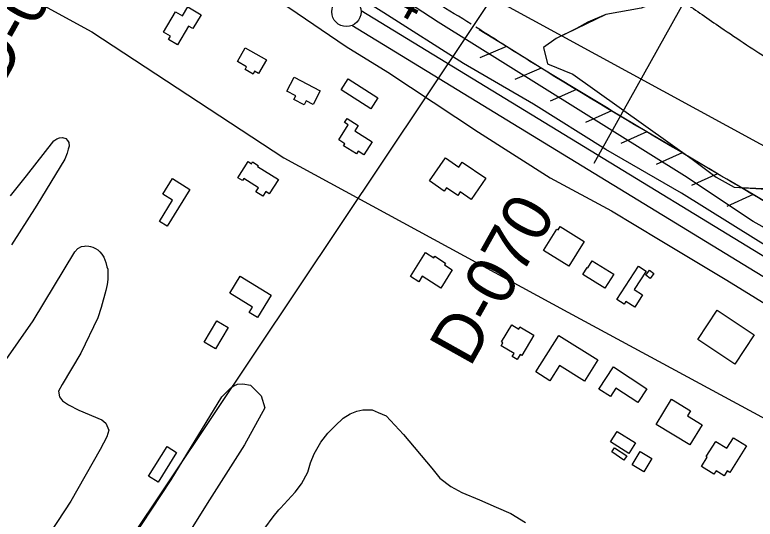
# Model space of a CAD drawing. Extents: x 3855477 to 3893699, y 299188 to 325115.
# Drawn here: x 3860680 to 3861941, y 312808 to 313668 of the extents above; entities that cross this region are included whole.
import ezdxf

# ---------------------------------------------------------------- set-up
doc = ezdxf.new("R2010")
doc.units = 0
for name, color, linetype in [('V-BLDG-OTLN', 7, 'Continuous'), ('V-LEVE-TOET', 7, 'Continuous'), ('V-RIVR-EDGE', 7, 'Continuous'), ('V-RIVR-RANG', 7, 'Continuous'), ('V-RIVR-RANG-IDEN', 7, 'Continuous'), ('V-ROAD-CNTR', 7, 'Continuous'), ('V-RRAP-FSHR', 7, 'Continuous'), ('V-SITE-VEGE', 7, 'Continuous'), ('V-SURV-LINE', 7, 'Continuous'), ('V-TOPO-SHOR', 7, 'Continuous')]:
    doc.layers.add(name, color=color, linetype=linetype)

msp = doc.modelspace()

# ---------------------------------------------------------------- linework, layer by layer
at = {"layer": 'V-BLDG-OTLN'}
for points in [[(3860933.2, 313638.2), (3860953.7, 313672.9), (3860965.7, 313665.8), (3860974.7, 313681.2), (3860997.2, 313667.9), (3860983.2, 313644.2), (3860976.1, 313648.4), (3860957.2, 313616.5), (3860941.8, 313625.6), (3860945.1, 313631.2)], [(3861072.6, 313611.6), (3861108.7, 313591.1), (3861095.3, 313567.5), (3861088.5, 313571.4), (3861085.9, 313566.8), (3861072.2, 313574.5), (3861074.8, 313579.1), (3861059.2, 313588)], [(3861155.8, 313561.4), (3861200.3, 313538.3), (3861188.2, 313515.1), (3861176.4, 313521.3), (3861172.8, 313514.2), (3861155.4, 313523.2), (3861158.6, 313529.4), (3861143.3, 313537.3)], [(3861286.3, 313507.5), (3861235.6, 313539.9), (3861247.7, 313558.8), (3861298.4, 313526.4)], [(3861288.4, 313451.4), (3861274.4, 313429.3), (3861264.8, 313435.4), (3861261.8, 313430.7), (3861240, 313444.5), (3861242.2, 313448.1), (3861231.7, 313454.7), (3861247.9, 313480.2), (3861241.6, 313484.3), (3861245.9, 313490.9), (3861264.5, 313479.1), (3861258.9, 313470.2)], [(3861386.2, 313384.6), (3861413.3, 313424), (3861436.4, 313408.2), (3861442.1, 313416.5), (3861481.9, 313389.1), (3861457.2, 313353.1), (3861438.5, 313365.8), (3861434.3, 313359.7), (3861415.1, 313372.9), (3861411.2, 313367.4)], [(3861128.9, 313387), (3861113.5, 313362.6), (3861107.5, 313366.4), (3861102.6, 313358.7), (3861090.6, 313366.3), (3861094.8, 313372.9), (3861070, 313388.6), (3861067.9, 313385.2), (3861059.9, 313390.2), (3861077.2, 313417.7), (3861083.1, 313414), (3861085.1, 313417.1), (3861094.6, 313411.1), (3861093.5, 313409.4)], [(3860978.4, 313370), (3860939.4, 313307.6), (3860926.3, 313315.8), (3860948.8, 313351.7), (3860932.2, 313362.2), (3860948.7, 313388.6)], [(3861580.4, 313265.9), (3861603.2, 313302.7), (3861605.5, 313301.3), (3861609, 313306.9), (3861649.6, 313281.6), (3861623.3, 313239.2)], [(3861353.9, 313222), (3861379.6, 313262.6), (3861393.6, 313253.7), (3861395.3, 313256.5), (3861413.7, 313244.8), (3861411.7, 313241.6), (3861425.1, 313233.1), (3861405.6, 313202.2), (3861374, 313222.2), (3861368.1, 313213)], [(3861663.5, 313248.7), (3861700.1, 313225.7), (3861685, 313201.7), (3861647.2, 313225.5), (3861654.5, 313237.3), (3861655.8, 313236.5)], [(3861705.4, 313182.4), (3861741.9, 313239.2), (3861754.9, 313230.9), (3861734.9, 313199.7), (3861749.1, 313190.6), (3861735.7, 313169.8), (3861720.7, 313179.5), (3861717.6, 313174.6)], [(3861064, 313222.3), (3861116.5, 313189.9), (3861093.1, 313152), (3861079.4, 313160.4), (3861085, 313169.4), (3861046.2, 313193.4)], [(3861768.1, 313227.1), (3861761.8, 313218.7), (3861754.7, 313224), (3861760.9, 313232.4)], [(3861906, 313072.5), (3861842.9, 313114.4), (3861876.1, 313164.4), (3861939.2, 313122.5)], [(3861043.4, 313135), (3861021.7, 313098.7), (3861002.7, 313110.1), (3861024.3, 313146.4)], [(3861563.8, 313121.8), (3861543.2, 313087.3), (3861540.7, 313088.8), (3861535.6, 313080.3), (3861527, 313085.4), (3861530.2, 313090.7), (3861508.1, 313103.9), (3861511.2, 313109), (3861509, 313110.3), (3861526.3, 313139.4), (3861538.2, 313132.3), (3861540.3, 313135.8)], [(3861606.7, 313121.6), (3861673.1, 313079.6), (3861650.1, 313043.3), (3861607.5, 313070.2), (3861591, 313044.2), (3861567.2, 313059.3)], [(3861699.3, 313067.9), (3861756.3, 313030.6), (3861740.8, 313006.9), (3861703.3, 313031.4), (3861694.2, 313017.3), (3861674.6, 313030.1)], [(3861825.4, 312984.6), (3861850.4, 312969.4), (3861829.4, 312934.9), (3861772, 312969.9), (3861798.1, 313012.7), (3861830.5, 312992.9)], [(3861705.6, 312958), (3861736.8, 312938.4), (3861725.4, 312920.3), (3861694.2, 312939.9)], [(3861903.7, 312947.1), (3861926, 312933.1), (3861897.4, 312887.8), (3861893.1, 312890.6), (3861887.9, 312882.4), (3861874.3, 312891), (3861870.5, 312884.9), (3861849.2, 312898.3), (3861859, 312913.8), (3861857.3, 312914.9), (3861873.7, 312941), (3861892.4, 312929.2)], [(3860939.4, 312932.2), (3860955.7, 312922), (3860924.1, 312871.2), (3860907.7, 312881.4)], [(3861701.3, 312930.2), (3861722, 312916.2), (3861717.2, 312909.1), (3861696.6, 312923.1)], [(3861744.9, 312923.8), (3861764.8, 312911.8), (3861751.1, 312889.1), (3861731.3, 312901.1)]]:
    msp.add_lwpolyline(points, close=True, dxfattribs=at)
at = {"layer": 'V-LEVE-TOET'}
for points in [[(3862242.2, 313100.5), (3862093.7, 313191.4), (3861941.9, 313285.1), (3861815.6, 313363.6), (3861686.6, 313438.4), (3861563.5, 313515.7), (3861444.2, 313584.7), (3861308.7, 313671.1), (3861176.5, 313754.8), (3861033.5, 313846.5), (3860865.7, 313952.6), (3860666.5, 314081.9), (3860455.2, 314218.1), (3860280.2, 314328.3), (3860126.5, 314425.9), (3859979.2, 314523.5), (3859824, 314623.6), (3859706.2, 314705.8), (3859691.7, 314716.1), (3859678.8, 314724.5), (3859655.1, 314737.6), (3859575.8, 314787.4), (3859572.3, 314789.8)], [(3860660.7, 313988.8), (3860749.4, 313935.7), (3860881.4, 313854.3), (3860919.6, 313826.5), (3860984.4, 313781.3), (3861077.1, 313725), (3861146.5, 313680.2), (3861244.1, 313613.7), (3861315.4, 313570), (3861469.8, 313467.8), (3861591.7, 313389.8), (3861695.9, 313333.8), (3861779.1, 313284), (3861892.7, 313215.5), (3861990.2, 313155.4)]]:
    msp.add_lwpolyline(points, dxfattribs=at)
at = {"layer": 'V-RIVR-EDGE'}
msp.add_spline([(3861230.3, 314081.8), (3861249.7, 314067.2), (3861271, 314053.5), (3861295.2, 314036.5), (3861330.6, 314011.6), (3861359.2, 313991.2), (3861386.9, 313974.6), (3861437.8, 313938), (3861477, 313912.7), (3861508.6, 313892.7), (3861539.1, 313865.9), (3861562.8, 313845.9), (3861578.8, 313831.8), (3861602.1, 313814.3), (3861632.6, 313795.8), (3861647.2, 313793.8), (3861661.3, 313794.2), (3861675.4, 313788.4), (3861690.4, 313775.2), (3861787.8, 313710.9), (3861820.8, 313688.4), (3861850.4, 313668), (3861882.4, 313646), (3861926, 313616.8), (3861968.7, 313589), (3861997.3, 313571.5), (3862045.8, 313537.8), (3862083.6, 313512), (3862115.6, 313489.6), (3862218.4, 313424.3), (3862268.8, 313390.6), (3862319.7, 313355.5), (3862352.2, 313333.6), (3862383.2, 313312.1), (3862411.3, 313296.1), (3862449.2, 313274.1), (3862514.1, 313236.1), (3862553.9, 313209.7), (3862585.4, 313189.3), (3862612.6, 313172.2), (3862627.1, 313164.9), (3862657.2, 313144.4), (3862694, 313121.5), (3862750.3, 313081.5), (3862777.9, 313064.5), (3862798.2, 313047.9), (3862816.2, 313034.8), (3862843.8, 313020.1), (3862877.8, 312998.7), (3862908.3, 312978.7), (3862931.1, 312966), (3862941.3, 312959.7), (3862968.9, 312940.2), (3862982, 312929.4), (3862992.2, 312919.2), (3863007.7, 312910.4), (3863022.2, 312900.2), (3863035.8, 312897.3), (3863052.8, 312895.3), (3863063, 312892.8), (3863077.1, 312883.6), (3863096.5, 312862.1), (3863112.9, 312841.7), (3863119.7, 312836.3), (3863132.3, 312835.8), (3863154.7, 312841.1), (3863171.2, 312846.9), (3863176.6, 312849.8), (3863182.9, 312852.2), (3863185.8, 312852.7), (3863189.2, 312849.3), (3863207.1, 312832.2)], degree=3, dxfattribs=at)
at = {"layer": 'V-RIVR-RANG'}
msp.add_line((3861666.5, 313414.8), (3862249.9, 314463.5), dxfattribs=at)
at = {"layer": 'V-ROAD-CNTR'}
for points in [[(3860065.6, 311560.2), (3863135.4, 316155.3)], [(3859576.8, 314448.8), (3859704.1, 314377.7), (3859828.9, 314304.1), (3859950.8, 314256.3), (3860168.7, 314112.6), (3860352.7, 313996.7), (3860439.6, 313939.9), (3860536.7, 313875), (3860586.7, 313830.8), (3860647.1, 313765.2), (3860678.8, 313720.8), (3860735.4, 313680.1), (3860811.3, 313638.9), (3861138, 313423.9), (3861621.8, 313160.8), (3862043.2, 312933.3), (3862208.5, 312832.9), (3862289.4, 312790.1)]]:
    msp.add_lwpolyline(points, dxfattribs=at)
at = {"layer": 'V-RRAP-FSHR'}
for p, q in [((3861517.1, 313613.4), (3861472.2, 313594.1)), ((3861576.6, 313576.5), (3861531.7, 313557.3)), ((3861636.5, 313540.3), (3861591.8, 313520.6)), ((3861696.4, 313504.1), (3861651.7, 313484.4)), ((3861756.5, 313468.3), (3861712, 313448.3)), ((3861816.6, 313432.4), (3861772.1, 313412.4)), ((3861876.9, 313396.8), (3861832.5, 313376.6)), ((3861937.2, 313361.3), (3861892.7, 313341))]:
    msp.add_line(p, q, dxfattribs=at)
for points in [[(3861446, 313723), (3864695.8, 311951.5), (3865854.4, 311447)], [(3861517.1, 313613.4), (3861470.8, 313642.1)], [(3861576.6, 313576.6), (3861569.9, 313580.7), (3861517.1, 313613.4)], [(3861636.5, 313540.3), (3861576.6, 313576.6)], [(3861696.4, 313504.1), (3861690.3, 313507.8), (3861636.5, 313540.3)], [(3861756.5, 313468.3), (3861696.4, 313504.1)], [(3861937.2, 313361.3), (3861892.7, 313387.5), (3861876.9, 313396.8), (3861816.6, 313432.4), (3861811.1, 313435.7), (3861756.5, 313468.3)], [(3861975.8, 313338.4), (3861974.3, 313339.4), (3861937.2, 313361.3)]]:
    msp.add_lwpolyline(points, dxfattribs=at)
for points in [[(3861457.3, 313651.6), (3861341.7, 313724.5), (3861042.6, 313929.1), (3860809.3, 314076), (3860704.8, 314143.3)], [(3861974.3, 313339.4), (3861811.1, 313435.7), (3861569.9, 313580.7), (3861465.3, 313646.6)]]:
    msp.add_spline(points, degree=3, dxfattribs=at)
at = {"layer": 'V-SITE-VEGE'}
for points in [[(3862123.3, 313211.7), (3861937.2, 313315.5), (3861820.4, 313393.4), (3861400.8, 313655.3), (3861082.9, 313863), (3860972.6, 313934.4), (3860656.8, 314137.9)], [(3861783.1, 313758.8), (3861799.7, 313741.3), (3861798.8, 313718), (3861783.7, 313698.6), (3861775, 313689.9), (3861746.9, 313679.1), (3861686.3, 313668.3), (3861656.1, 313655.3), (3861636.6, 313644.5), (3861602, 313627.2), (3861580.4, 313612), (3861586.9, 313583.9), (3861630.1, 313566.6), (3861833.4, 313421.6), (3861874.5, 313391.3), (3861904.8, 313374), (3861954.5, 313371.8)], [(3860672.5, 313359.1), (3860699.9, 313393.2), (3860746.8, 313453.1), (3860751.7, 313456.5), (3860756.5, 313458), (3860761.5, 313458.4), (3860767, 313456.8), (3860770, 313453.5), (3860771.9, 313450), (3860772.4, 313443.7), (3860771.2, 313438.7), (3860769.1, 313431.8), (3860765.1, 313422), (3860717.9, 313343.3), (3860674.7, 313275.8)], [(3860661.3, 313074.7), (3860711.1, 313146.4), (3860782.3, 313264.1), (3860787.2, 313269.5), (3860793.9, 313272.7), (3860798.6, 313273.6), (3860801.2, 313273.9), (3860806, 313273.7), (3860809.1, 313273.1), (3860812.9, 313271.9), (3860817.3, 313269.7), (3860821.5, 313267.2), (3860825.1, 313263.7), (3860828.4, 313259.6), (3860831.8, 313254.8), (3860835.1, 313245.7), (3860837, 313238.2), (3860838.3, 313234.2), (3860838.4, 313229.6), (3860838.7, 313225.6), (3860838.7, 313216.7), (3860837.4, 313208.1), (3860835.2, 313198.1), (3860827.4, 313169.1), (3860821.7, 313151.3), (3860792.3, 313091.1), (3860761, 313037.7), (3860754.6, 313026.3), (3860756.1, 313016.9), (3860761.2, 313010.1), (3860771.6, 313003.2), (3860789.2, 312994.1), (3860828.1, 312977.5), (3860834.9, 312971.7), (3860840, 312960.1), (3860836.7, 312948.7), (3860825.5, 312926.9), (3860775.4, 312839.3), (3860659.7, 312662.2)], [(3860811.3, 312670.5), (3860946.3, 312875.6), (3861032.7, 313016.7), (3861047.8, 313032.1), (3861053.2, 313035.6), (3861059.2, 313038.5), (3861068.2, 313039), (3861081.3, 313036.5), (3861090.1, 313028), (3861099.6, 313018.3), (3861105.9, 312998), (3861071.2, 312935), (3861011.6, 312841.4), (3860932.5, 312715.1)]]:
    msp.add_lwpolyline(points, dxfattribs=at)
at = {"layer": 'V-SURV-LINE'}
for points in [[(3861269.7, 313675), (3862328.4, 313028.5)], [(3862312.8, 313002.9), (3861254, 313649.4)]]:
    msp.add_lwpolyline(points, dxfattribs=at)
msp.add_circle((3861244.8, 313672.6), 25, dxfattribs=at)
at = {"layer": 'V-TOPO-SHOR'}
for points in [[(3861799.7, 313741.3), (3861798.8, 313718), (3861775, 313689.9), (3861746.9, 313679.1), (3861686.3, 313668.3), (3861602, 313627.2), (3861580.4, 313612), (3861586.9, 313583.9), (3861630.1, 313566.6), (3861630.1, 313566.6), (3861833.4, 313421.6), (3861874.5, 313391.3), (3861904.8, 313374), (3861978.3, 313369.6)], [(3861106, 312792.9), (3861120, 312812.5), (3861129.7, 312824.3), (3861132.7, 312827.3), (3861157.5, 312854.5), (3861168.4, 312868.7), (3861178.8, 312888.3), (3861183.7, 312904.3), (3861189.9, 312919.8), (3861201.4, 312939.4), (3861213, 312954.8), (3861225.7, 312967.7), (3861239.5, 312980.7), (3861251, 312987.8), (3861262.4, 312992.4), (3861272.6, 312994.7), (3861288.7, 312994.5), (3861298.8, 312990.2), (3861312.5, 312984.7), (3861341.9, 312952.7), (3861390.3, 312895.4), (3861403.8, 312878.5), (3861422.8, 312864), (3861441.1, 312853.6), (3861471.5, 312841.3), (3861500, 312829), (3861524.9, 312818), (3861549.9, 312802.8)]]:
    msp.add_lwpolyline(points, dxfattribs=at)

# ---------------------------------------------------------------- texts
at = {"layer": 'V-RIVR-RANG'}
msp.add_text('9.4', height=67, rotation=330.8083, dxfattribs=at).set_placement((3861250.3, 313715.1))
at = {"layer": 'V-RIVR-RANG-IDEN'}
for s, rotation, p in [('D-060', 60.7693, (3860657.4, 313542.7)), ('D-070', 60.7713, (3861455.2, 313065.5))]:
    msp.add_text(s, height=83, rotation=rotation, dxfattribs=at).set_placement(p)

doc.saveas('drawing.dxf')
